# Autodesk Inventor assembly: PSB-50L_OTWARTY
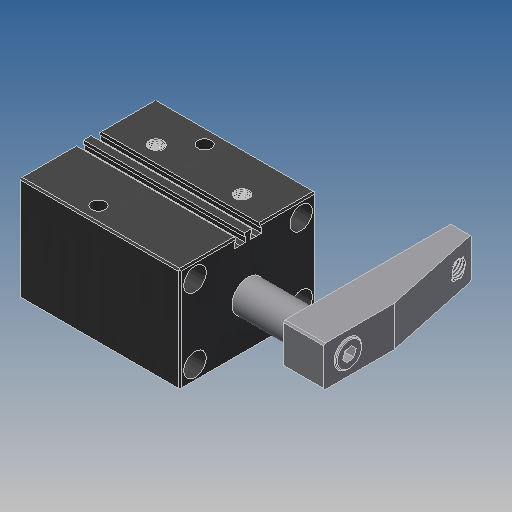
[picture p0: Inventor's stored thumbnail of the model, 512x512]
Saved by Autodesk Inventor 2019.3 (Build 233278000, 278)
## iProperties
Created: 2010-02
Part Number: PSB-50L_OTWARTY
Material: Ogólny
Document SubType Name: Assembly
Designer: CADENGINEERING4
Sending System: PRO/ENGINEER BY PARAMETRIC TECHNOLOGY CORPORATION, 2007170
Preprocessor: PRO/ENGINEER BY PARAMETRIC TECHNOLOGY CORPORATION, 2007170
Title: PSB-50_ASM
Author: Administrator
Revision Number: 1LAST_VERSION
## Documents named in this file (6)
- E:\SERWER_ZAPAS\Pneumatic\PSB PNEUMATIC SWING\PSB-50\PSB-50L_OTWARTY.iam
- E:\SERWER_ZAPAS\Pneumatic\PSB PNEUMATIC SWING\PSB-50\PSB-50BT.ipt
- E:\SERWER_ZAPAS\Pneumatic\PSB PNEUMATIC SWING\PSB-50\PSB-50HSG.ipt
- E:\SERWER_ZAPAS\Pneumatic\PSB PNEUMATIC SWING\PSB-50\PSB-50HG.ipt
- E:\SERWER_ZAPAS\Pneumatic\PSB PNEUMATIC SWING\PSB-50\PSB-50YB.ipt
- E:\SERWER_ZAPAS\Pneumatic\PSB PNEUMATIC SWING\PSB-50\M10LC.ipt
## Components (5 placed, 5 different names)
1. PSB-50BT_0 — Zestawiające:6, Zestawiające:7, Kątowe:1
2. PSB-50HSG_1 — Zestawiające:1, Zestawiające:4, Zestawiające:6, Zestawiające:7
3. PSB-50HG_2
4. PSB-50YB_3 — Zestawiające:1, Zestawiające:2, Zestawiające:4, Zestawiające:5, Kątowe:1
5. M10LC_4 — Zestawiające:2, Zestawiające:5
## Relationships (7: Mate 6, Angle 1)
- Zestawiające:1 [Mate]: PSB-50HSG_1 ↔ PSB-50YB_3
- Zestawiające:2 [Mate]: PSB-50YB_3 ↔ M10LC_4
- Zestawiające:4 [Mate]: PSB-50HSG_1 ↔ PSB-50YB_3
- Zestawiające:5 [Mate]: PSB-50YB_3 ↔ M10LC_4
- Zestawiające:6 [Mate]: PSB-50BT_0 ↔ PSB-50HSG_1
- Zestawiające:7 [Mate]: PSB-50BT_0 ↔ PSB-50HSG_1
- Kątowe:1 [Angle]: PSB-50BT_0 ↔ PSB-50YB_3
